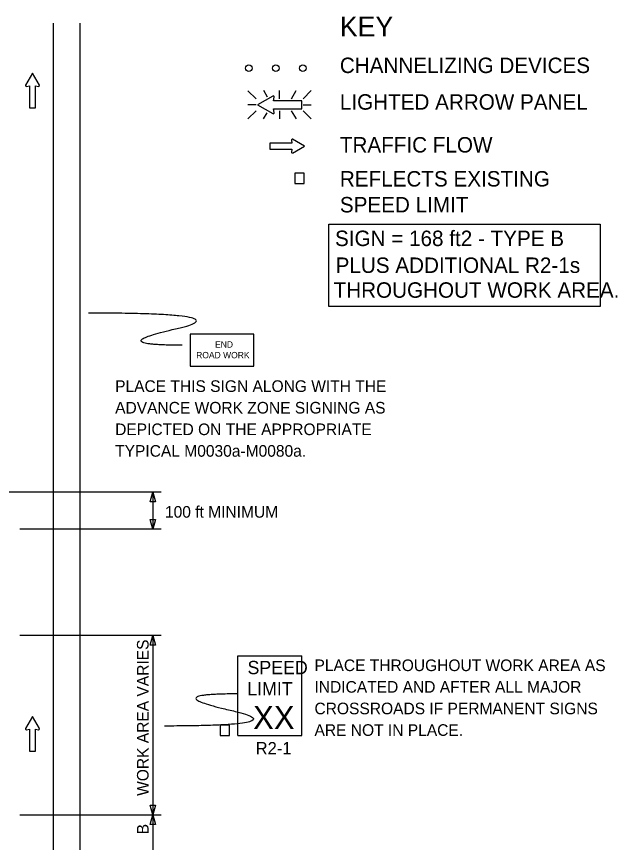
# Model space of a CAD drawing. Extents: x 16796 to 18475, y 7218 to 8209.
# Drawn here: x 17063.3 to 17425.1, y 7711.6 to 8209 of the extents above; entities that cross this region are included whole.
import ezdxf

# ---------------------------------------------------------------- set-up
doc = ezdxf.new("R2010")
doc.units = 0
for name, color, linetype in [('MT_SCRATCH_LEVEL_E', 7, 'Continuous'), ('PAVT_EDGE_EX', 7, 'Continuous'), ('TRAFFIC_SIGNS_PR', 7, 'Continuous'), ('TYPICAL_TEXT_DIMEN_EX', 7, 'Continuous'), ('TYPICAL_TEXT_DIMEN_PR', 7, 'Continuous')]:
    doc.layers.add(name, color=color, linetype=linetype)

msp = doc.modelspace()

# ---------------------------------------------------------------- linework, layer by layer
at = {"layer": 'MT_SCRATCH_LEVEL_E'}
for p, q in [((17072.85, 8174.82), (17068.74, 8167.58)), ((17072.85, 8174.82), (17068.74, 8167.58)), ((17077, 8167.58), (17072.85, 8174.82)), ((17077, 8167.58), (17072.85, 8174.82)), ((17069.22, 8166.9), (17071, 8167.22)), ((17069.22, 8166.9), (17071, 8167.22)), ((17071, 8167.22), (17071, 8153.96)), ((17071, 8167.22), (17071, 8153.96)), ((17074.74, 8153.96), (17074.74, 8167.22)), ((17074.74, 8167.22), (17076.52, 8166.9)), ((17074.74, 8153.96), (17074.74, 8167.22)), ((17074.74, 8167.22), (17076.52, 8166.9)), ((17071, 8153.96), (17074.74, 8153.96)), ((17071, 8153.96), (17074.74, 8153.96)), ((17229.11, 8132.78), (17215.85, 8132.78)), ((17215.85, 8132.78), (17215.85, 8129.04)), ((17229.11, 8132.78), (17215.85, 8132.78)), ((17215.85, 8132.78), (17215.85, 8129.04)), ((17228.79, 8134.56), (17229.11, 8132.78)), ((17228.79, 8134.56), (17229.11, 8132.78)), ((17236.71, 8130.93), (17229.47, 8135.04)), ((17236.71, 8130.93), (17229.47, 8135.04)), ((17215.85, 8129.04), (17229.11, 8129.04)), ((17215.85, 8129.04), (17229.11, 8129.04)), ((17229.11, 8129.04), (17228.79, 8127.26)), ((17229.11, 8129.04), (17228.79, 8127.26)), ((17229.47, 8126.78), (17236.71, 8130.93)), ((17229.47, 8126.78), (17236.71, 8130.93)), ((17072.85, 7787.39), (17068.74, 7780.15)), ((17072.85, 7787.39), (17068.74, 7780.15)), ((17077, 7780.15), (17072.85, 7787.39)), ((17077, 7780.15), (17072.85, 7787.39)), ((17069.22, 7779.47), (17071, 7779.78)), ((17069.22, 7779.47), (17071, 7779.78)), ((17071, 7779.78), (17071, 7766.52)), ((17071, 7779.78), (17071, 7766.52)), ((17074.74, 7766.52), (17074.74, 7779.78)), ((17074.74, 7779.78), (17076.52, 7779.47)), ((17074.74, 7766.52), (17074.74, 7779.78)), ((17074.74, 7779.78), (17076.52, 7779.47)), ((17071, 7766.52), (17074.74, 7766.52)), ((17071, 7766.52), (17074.74, 7766.52))]:
    msp.add_line(p, q, dxfattribs=at)
for centre, start, end in [((17069.15, 8167.36), 150.4248, 279.9638), ((17069.15, 8167.36), 150.4248, 279.9638), ((17076.59, 8167.36), 260.0362, 29.7731), ((17076.59, 8167.36), 260.0362, 29.7731), ((17229.25, 8134.63), 60.4248, 189.9638), ((17229.25, 8134.63), 60.4248, 189.9638), ((17229.25, 8127.19), 170.0362, 299.7731), ((17229.25, 8127.19), 170.0362, 299.7731), ((17069.15, 7779.93), 150.4248, 279.9638), ((17069.15, 7779.93), 150.4248, 279.9638), ((17076.59, 7779.93), 260.0362, 29.7731), ((17076.59, 7779.93), 260.0362, 29.7731)]:
    msp.add_arc(centre, 0.463, start, end, dxfattribs=at)
at = {"layer": 'PAVT_EDGE_EX'}
for p, q in [((17085.33, 8204.89), (17085.33, 7353.77)), ((17101.33, 8204.89), (17101.33, 7353.77))]:
    msp.add_line(p, q, dxfattribs=at)
at = {"layer": 'TRAFFIC_SIGNS_PR'}
for p, q in [((17202.53, 8164.31), (17207.46, 8159.38)), ((17214.29, 8160.49), (17212.08, 8164.32)), ((17221.61, 8159.38), (17221.61, 8164.32)), ((17228.84, 8159.38), (17231.69, 8164.32)), ((17235.76, 8159.38), (17240.69, 8164.32)), ((17207.46, 8155.82), (17202.53, 8155.82)), ((17202.53, 8147.34), (17207.46, 8152.27)), ((17221.61, 8152.27), (17221.61, 8147.33)), ((17231.74, 8147.33), (17228.89, 8152.27)), ((17235.76, 8155.82), (17240.69, 8155.82)), ((17235.76, 8152.27), (17240.69, 8147.33)), ((17212.04, 8147.33), (17214.15, 8151)), ((17196.56, 7824.09), (17234.96, 7824.09)), ((17196.56, 7776.09), (17196.56, 7824.09)), ((17234.96, 7776.09), (17234.96, 7824.09)), ((17196.56, 7776.09), (17234.96, 7776.09))]:
    msp.add_line(p, q, dxfattribs=at)
for points in [[(17217.54, 8161.1), (17208.25, 8155.82), (17217.54, 8150.5)], [(17218.41, 8151.13), (17218.01, 8153.4), (17235.02, 8153.4), (17235.02, 8158.2), (17218.01, 8158.2), (17218.41, 8160.48)]]:
    msp.add_lwpolyline(points, dxfattribs=at)
for points in [[(17230.87, 8108.45), (17236.47, 8108.45), (17236.47, 8114.62), (17230.87, 8114.62)], [(17167.8, 7998.43), (17206.2, 7998.43), (17206.2, 8017.63), (17167.8, 8017.63)], [(17185.95, 7776.09), (17191.55, 7776.09), (17191.55, 7782.26), (17185.95, 7782.26)]]:
    msp.add_lwpolyline(points, close=True, dxfattribs=at)
for centre in [(17203.09, 8177.86), (17219.39, 8177.86), (17235.69, 8177.86)]:
    msp.add_circle(centre, 2, dxfattribs=at)
for centre, radius, start, end in [((17217.82, 8160.58), 0.598, 350.7308, 118.8916), ((17217.82, 8151.03), 0.597, 241.4833, 9.9593)]:
    msp.add_arc(centre, radius, start, end, dxfattribs=at)
for points in [[(17163.05, 8011.03), (17115.82, 8011.03), (17200.84, 8030.37), (17106.54, 8030.37)], [(17196.09, 7801.07), (17148.86, 7801.07), (17233.88, 7781.72), (17152.4, 7781.72)]]:
    msp.add_open_spline(points, degree=2, dxfattribs=at)
at = {"layer": 'TYPICAL_TEXT_DIMEN_EX'}
msp.add_lwpolyline([(17251.24, 8083.91), (17414.58, 8083.91), (17414.58, 8034.34), (17251.24, 8034.34)], close=True, dxfattribs=at)
at = {"layer": 'TYPICAL_TEXT_DIMEN_PR'}
for p, q in [((17150.33, 7922.49), (17042.86, 7922.49)), ((17143.76, 7916.63), (17145.33, 7922.49)), ((17145.33, 7922.49), (17145.33, 7900.29)), ((17145.33, 7922.49), (17146.9, 7916.63)), ((17145.33, 7916.63), (17143.76, 7916.63)), ((17146.9, 7916.63), (17145.33, 7916.63)), ((17145.33, 7900.29), (17143.76, 7906.15)), ((17143.76, 7906.15), (17145.33, 7906.15)), ((17145.33, 7906.15), (17146.9, 7906.15)), ((17146.9, 7906.15), (17145.33, 7900.29)), ((17150.33, 7900.29), (17065.19, 7900.29)), ((17150.33, 7836.29), (17065.19, 7836.29)), ((17143.76, 7830.43), (17145.33, 7836.29)), ((17143.76, 7830.43), (17145.33, 7836.29)), ((17145.33, 7836.29), (17145.33, 7728.31)), ((17145.33, 7836.29), (17146.9, 7830.43)), ((17145.33, 7836.29), (17146.9, 7830.43)), ((17145.33, 7830.43), (17143.76, 7830.43)), ((17145.33, 7830.43), (17143.76, 7830.43)), ((17146.9, 7830.43), (17145.33, 7830.43)), ((17146.9, 7830.43), (17145.33, 7830.43)), ((17145.33, 7728.31), (17143.76, 7734.17)), ((17143.76, 7734.17), (17145.33, 7734.17)), ((17145.33, 7728.31), (17143.76, 7734.17)), ((17143.76, 7734.17), (17145.33, 7734.17)), ((17145.33, 7734.17), (17146.9, 7734.17)), ((17146.9, 7734.17), (17145.33, 7728.31)), ((17145.33, 7734.17), (17146.9, 7734.17)), ((17146.9, 7734.17), (17145.33, 7728.31)), ((17065.19, 7728.31), (17150.33, 7728.31)), ((17143.76, 7722.44), (17145.33, 7728.31)), ((17143.76, 7722.44), (17145.33, 7728.31)), ((17145.33, 7728.31), (17145.33, 7704.31)), ((17145.33, 7728.31), (17146.9, 7722.44)), ((17145.33, 7728.31), (17146.9, 7722.44)), ((17145.33, 7722.44), (17143.76, 7722.44)), ((17145.33, 7722.44), (17143.76, 7722.44)), ((17146.9, 7722.44), (17145.33, 7722.44)), ((17146.9, 7722.44), (17145.33, 7722.44))]:
    msp.add_line(p, q, dxfattribs=at)

# ---------------------------------------------------------------- texts
at = {"layer": 'TRAFFIC_SIGNS_PR'}
for s, height, p in [('END', 3.831, (17182.8, 8009.56)), ('ROAD WORK', 3.831, (17171.41, 8003.18)), ('PLACE THIS SIGN ALONG WITH THE', 7, (17122.64, 7982.9)), ('ADVANCE WORK ZONE SIGNING AS', 7, (17122.64, 7969.9)), ('DEPICTED ON THE APPROPRIATE', 7, (17122.64, 7956.9)), ('TYPICAL M0030a-M0080a.', 7, (17122.64, 7943.9)), ('SPEED', 8, (17202.33, 7812.95)), ('PLACE THROUGHOUT WORK AREA AS', 7, (17242.66, 7814.8)), ('INDICATED AND AFTER ALL MAJOR', 7, (17242.66, 7801.8)), ('LIMIT', 8, (17202.17, 7800.15)), ('XX', 14.031, (17205.67, 7779.85)), ('CROSSROADS IF PERMANENT SIGNS', 7, (17242.66, 7788.8)), ('ARE NOT IN PLACE.', 7, (17242.66, 7775.8)), ('R2-1', 7.44, (17207.24, 7764.65))]:
    msp.add_text(s, height=height, dxfattribs=at).set_placement(p)
at = {"layer": 'TYPICAL_TEXT_DIMEN_EX'}
for s, height, p in [('KEY', 12, (17257.93, 8196.97)), ('CHANNELIZING DEVICES', 9.3, (17257.93, 8174.92)), ('LIGHTED ARROW PANEL', 9.3, (17257.93, 8152.87)), ('TRAFFIC FLOW', 9.3, (17257.93, 8127.07)), ('REFLECTS EXISTING', 9.3, (17257.93, 8106.6)), ('SPEED LIMIT', 9.3, (17257.93, 8091)), ('SIGN = 168 ft2 - TYPE B', 9.3, (17255.01, 8070.74)), ('PLUS ADDITIONAL R2-1s', 9.3, (17255.38, 8054.56)), ('THROUGHOUT WORK AREA.', 9.3, (17254.17, 8039.62))]:
    msp.add_text(s, height=height, dxfattribs=at).set_placement(p)
at = {"layer": 'TYPICAL_TEXT_DIMEN_PR'}
msp.add_text('100 ft MINIMUM', height=7, dxfattribs=at).set_placement((17152.64, 7907.18))
for s, p in [('WORK AREA VARIES', (17142.78, 7739.66)), ('B', (17142.78, 7716.54))]:
    msp.add_text(s, height=7, rotation=90, dxfattribs=at).set_placement(p)

doc.saveas('drawing.dxf')
